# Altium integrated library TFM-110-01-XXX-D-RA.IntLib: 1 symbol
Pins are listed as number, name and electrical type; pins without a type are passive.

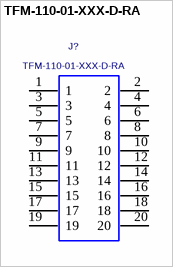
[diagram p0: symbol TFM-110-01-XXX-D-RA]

## TFM-110-01-XXX-D-RA
designator J?
0.050" RIGHT ANGLE TERMINAL STRIP, 20PINS.; MANUFACTURER: SAMTEC
footprint TFM-110-01-XXX-D-RA
pins: 1, 2, 3, 4, 5, 6, 7, 8, 9, 10, 11, 12, 13, 14, 15, 16, 17, 18, 19, 20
